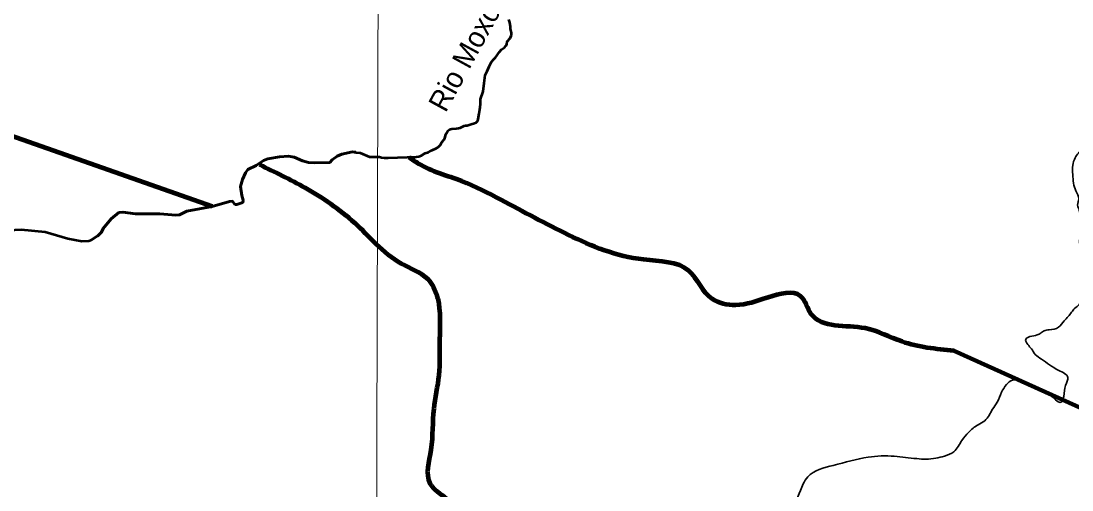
# Model space of a CAD drawing. Extents: x 553962 to 842807, y 8883888 to 9032388.
# Drawn here: x 601258 to 626649, y 8979769 to 8991098 of the extents above; entities that cross this region are included whole.
import ezdxf
from ezdxf.enums import TextEntityAlignment as Align

# ---------------------------------------------------------------- set-up
doc = ezdxf.new("R2010")
doc.units = 0
doc.header["$LTSCALE"] = 150
doc.linetypes.add('LONG_DASH_SHORT_DASH', pattern=[9.9, 6, -1.2, 1.5, -1.2])
for name, color, linetype, lineweight in [('1', 7, 'Continuous', 13), ('20', 7, 'Continuous', 35), ('24', 7, 'Continuous', 25), ('7', 7, 'LONG_DASH_SHORT_DASH', 60), ('9', 7, 'Continuous', 90)]:
    doc.layers.add(name, color=color, linetype=linetype, lineweight=lineweight)
doc.layers.add('49', color=7, linetype='Continuous')

msp = doc.modelspace()

# ---------------------------------------------------------------- linework, layer by layer
at = {"layer": '1'}
msp.add_lwpolyline([(609971.9, 9023551.8), (609764.7, 8949706.7), (609734.2, 8939404.4)], dxfattribs=at)
at = {"layer": '20'}
for points in [[(629440.7, 8990481.7), (629370.8, 8990367.6), (629157.1, 8990237.3), (629038.6, 8990213.7), (628766.6, 8990128.3), (628527.1, 8990078.5), (628266.9, 8990114.4), (627868.3, 8990076), (627513, 8989997.6), (627211.3, 8989811.1), (627131.4, 8989676.8), (627004.5, 8989388.2), (626896.7, 8988882.7), (626926.1, 8988633.1), (627053.8, 8988394.4), (627065.2, 8988197.6), (626899.8, 8988002.1), (626727, 8987796.4), (626667.6, 8987611.7), (626669.1, 8987389.7), (626688.1, 8987182.9), (626744.8, 8986994.1), (626811.6, 8986805.4), (626784.8, 8986651.2), (626823.5, 8986530.4), (626873, 8986288.6), (626889.5, 8986071.7), (626831, 8985753.3), (626882.8, 8985544.3), (626929.8, 8985304.9), (626885.6, 8984716.7), (626851.4, 8984542.3), (626820.5, 8984249.4), (626720.1, 8984162.8), (626639.9, 8984066.3), (626554.8, 8983957.2), (626457, 8983855.5), (626326.8, 8983700.6), (626095, 8983638.2), (625976.5, 8983614.6), (625901.1, 8983563.6), (625810.6, 8983515), (625631.6, 8983473.2), (625531.1, 8983404.3), (625579.8, 8983283.6), (625668.8, 8983178.3), (625763.1, 8983045.3), (625910.2, 8982930.3), (626328.4, 8982658.5), (626549.1, 8982486), (626494.8, 8982296.4), (626451.1, 8982031.1), (626383.9, 8981889.3), (626165.9, 8982026.4), (625922.7, 8982170.9), (625386.1, 8982398.9), (625214.3, 8982422.9), (625066.1, 8982313.2), (624946.2, 8982128.1), (624841.7, 8981890.1), (624729.2, 8981717.7), (624541.7, 8981441.2), (624380.8, 8981344.1), (624152.3, 8981160.7), (623989.5, 8980967.7), (623796.9, 8980693.7), (623570.4, 8980588.5), (623356.2, 8980533.9), (622896.9, 8980525.3), (622356.3, 8980584.3), (621725.5, 8980561.8), (620881.2, 8980363.6), (620267.1, 8980088.9), (620154.7, 8979914), (619893.6, 8979296.3), (619818.7, 8979169.5), (619728.9, 8978997.3), (619561.3, 8978766.4), (619441.4, 8978568.6), (619379.5, 8978391.5), (619392.8, 8978285.7), (619437, 8978086.7), (619556.3, 8977976.6), (619791.4, 8977917.8), (620167.8, 8977875.2), (620455.5, 8977869.9), (620720.6, 8977864.3), (621089.4, 8977816.7), (621432.7, 8977821.8), (621673.8, 8977601.6), (622032.5, 8977315.6)], [(622032.5, 8977315.6), (621673.8, 8977601.6), (621432.7, 8977821.8), (621089.4, 8977816.7), (620720.6, 8977864.3), (620455.5, 8977869.9), (620167.8, 8977875.2), (619791.4, 8977917.8), (619556.3, 8977976.6), (619437, 8978086.7), (619392.8, 8978285.7), (619379.5, 8978391.5), (619441.4, 8978568.6), (619561.3, 8978766.4), (619728.9, 8978997.3), (619818.7, 8979169.5), (619893.6, 8979296.3), (620154.7, 8979914), (620267.1, 8980088.9), (620881.2, 8980363.6), (621725.5, 8980561.8), (622356.3, 8980584.3), (622896.9, 8980525.3), (623356.2, 8980533.9), (623570.4, 8980588.5), (623796.9, 8980693.7), (623989.5, 8980967.7), (624152.3, 8981160.7), (624380.8, 8981344.1), (624541.7, 8981441.2), (624729.2, 8981717.7), (624841.7, 8981890.1), (624946.2, 8982128.1), (625066.1, 8982313.2), (625214.3, 8982422.9), (625386.1, 8982398.9), (625922.7, 8982170.9), (626165.9, 8982026.4), (626383.9, 8981889.3), (626451.1, 8982031.1), (626494.8, 8982296.4), (626549.1, 8982486), (626328.4, 8982658.5), (625910.2, 8982930.3), (625763.1, 8983045.3), (625668.8, 8983178.3), (625579.8, 8983283.6), (625531.1, 8983404.3), (625631.6, 8983473.2), (625810.6, 8983515), (625901.1, 8983563.6), (625976.5, 8983614.6), (626095, 8983638.2), (626326.8, 8983700.6), (626457, 8983855.5), (626554.8, 8983957.2), (626639.9, 8984066.3), (626720.1, 8984162.8), (626820.5, 8984249.4), (626851.4, 8984542.3), (626885.6, 8984716.7), (626929.8, 8985304.9), (626882.8, 8985544.3), (626831, 8985753.3), (626889.5, 8986071.7), (626873, 8986288.6), (626823.5, 8986530.4), (626784.8, 8986651.2), (626811.6, 8986805.4), (626744.8, 8986994.1), (626688.1, 8987182.9), (626669.1, 8987389.7), (626667.6, 8987611.7), (626727, 8987796.4), (626899.8, 8988002.1), (627065.2, 8988197.6), (627053.8, 8988394.4), (626926.1, 8988633.1), (626896.7, 8988882.7), (627004.5, 8989388.2), (627131.4, 8989676.8), (627211.3, 8989811.1), (627513, 8989997.6), (627868.3, 8990076), (628266.9, 8990114.4), (628527.1, 8990078.5), (628766.6, 8990128.3), (629038.6, 8990213.7), (629157.1, 8990237.3), (629370.8, 8990367.6), (629440.7, 8990481.7)]]:
    msp.add_spline(points, degree=3, dxfattribs=at)
at = {"layer": '24', "lineweight": 53}
for points in [[(612374.7, 8989257.2), (612410.1, 8989349.2), (612422.8, 8989393.2), (612443.9, 8989595.2), (612472.1, 8989790.2), (612521.4, 8989889.2), (612567.7, 8990001.2), (612623.5, 8990108.2), (612679.4, 8990175.2), (612720.8, 8990217.2), (612815.3, 8990351.2), (612864.4, 8990407.2), (612937.9, 8990460.2), (612974.6, 8990496.2), (612997.1, 8990536.2), (613004.6, 8990605.2), (613071.9, 8990685.2), (613099.4, 8990741.2), (613104.8, 8990769.2), (613104.8, 8990813.2), (613086.3, 8990905.2), (613085.9, 8990954.2), (613066.1, 8991064.2), (613044.7, 8991133.2)], [(610812.6, 8987820.3), (610868.6, 8987825.3), (610933, 8987849.3), (611023.7, 8987905.3), (611105.7, 8987931.3), (611174.3, 8987972.3), (611295.8, 8988024.3), (611334, 8988050.3), (611392.2, 8988106.3), (611428.2, 8988171.3), (611476.2, 8988225.3), (611496.6, 8988270.3), (611519.8, 8988356.3), (611535.1, 8988392.3), (611570.6, 8988443.3), (611611.3, 8988477.3), (611633.5, 8988486.3), (611663.2, 8988493.3), (611778.5, 8988500.3), (611831.3, 8988507.2), (611867.2, 8988517.2), (611960.5, 8988564.2), (611993.5, 8988570.2), (612040.4, 8988571.2), (612135.1, 8988609.2), (612211, 8988629.2), (612253, 8988646.2), (612280.4, 8988668.2), (612294.2, 8988690.2), (612304.8, 8988723.2), (612325, 8988861.2), (612344.1, 8988963.2), (612347.8, 8989019.2), (612358.9, 8989089.2), (612362.3, 8989210.2), (612374.7, 8989257.2)], [(608722.9, 8987680.8), (608777.9, 8987747.6), (608897.1, 8987833.6), (609009.5, 8987880.2), (609264.4, 8987935.4), (609356.3, 8987924.6)], [(609356.3, 8987924.6), (609448.1, 8987913.7), (609678.6, 8987816.5)], [(606420.8, 8986668), (606473.8, 8986668.1), (606613.3, 8986714.2), (606626.1, 8986769), (606594.2, 8986880), (606564.5, 8987100.6), (606609.1, 8987266.3), (606681.2, 8987431.8), (606741, 8987512.8), (606939.6, 8987610), (607118.9, 8987727.3), (607224.8, 8987767.6), (607501, 8987816.5), (607722.2, 8987831.4), (607811.1, 8987818.7)], [(607811.1, 8987818.7), (607857.5, 8987812), (608058.1, 8987723), (608202.2, 8987682.7), (608346.4, 8987672.1), (608722.9, 8987680.8)], [(609678.6, 8987816.5), (609919.3, 8987814.4), (609966, 8987801.4), (610032.6, 8987795.3), (610127.9, 8987794.3), (610812.6, 8987820.3)], [(604502.8, 8986438.7), (604614.5, 8986437.8), (604995.5, 8986406.1), (605088.3, 8986418.9), (605266.8, 8986501.7), (605873.8, 8986618.4), (606294.7, 8986737.4), (606369.1, 8986745.7), (606420.8, 8986668)], [(603138.8, 8985934.3), (603201.3, 8985995.2), (603246.4, 8986085.3), (603439.7, 8986316.8), (603622.3, 8986468.1), (603715.8, 8986478.2), (604022, 8986442.1), (604249.4, 8986440.5), (604502.8, 8986438.7)], [(600614.3, 8986048.6), (600805.6, 8986038.6), (601260, 8986057.6), (601842, 8986004.5), (602386.1, 8985845.2), (602725.9, 8985781.5), (602895.9, 8985787.9), (602963.8, 8985811.2), (603100.1, 8985896.5), (603138.8, 8985934.3)]]:
    msp.add_lwpolyline(points, dxfattribs=at)
at = {"layer": '7', "lineweight": 35}
msp.add_line((610685.7, 8987847), (610687.2, 8987846.5), dxfattribs=at)
at = {"layer": '7'}
msp.add_line((603104.5, 8985900.8), (603138.8, 8985934.3), dxfattribs=at)
for points in [[(608722.9, 8987680.8), (608777.9, 8987747.6), (608897.1, 8987833.6), (609009.5, 8987880.2), (609264.4, 8987935.4), (609347, 8987925.7)], [(606420.8, 8986668), (606473.8, 8986668.1), (606613.3, 8986714.2), (606626.1, 8986769), (606594.2, 8986880), (606564.5, 8987100.6), (606609.1, 8987266.3), (606681.2, 8987431.8), (606741, 8987512.8), (606939.6, 8987610), (607118.9, 8987727.3), (607224.8, 8987767.6), (607501, 8987816.5), (607722.2, 8987831.4), (607811.1, 8987818.7)], [(607811.1, 8987818.7), (607857.5, 8987812), (608058.1, 8987723), (608202.2, 8987682.7), (608346.4, 8987672.1), (608722.9, 8987680.8)], [(604502.8, 8986438.7), (604614.5, 8986437.8), (604995.5, 8986406.1), (605088.3, 8986418.9), (605266.8, 8986501.7), (605873.8, 8986618.4), (606294.7, 8986737.4), (606369.1, 8986745.7), (606420.8, 8986668)], [(603138.8, 8985934.3), (603201.3, 8985995.2), (603246.4, 8986085.3), (603439.7, 8986316.8), (603622.3, 8986468.1), (603715.8, 8986478.2), (604022, 8986442.1), (604249.4, 8986440.5), (604502.8, 8986438.7)]]:
    msp.add_lwpolyline(points, dxfattribs=at)
at = {"layer": '9'}
for points in [[(605873.8, 8986618.4), (590956.6, 8991866.7), (589163, 9005713.7)], [(637260.6, 8972975.8), (637390.8, 8977204.2), (635350.7, 8977923.9), (623791.9, 8983133)]]:
    msp.add_lwpolyline(points, dxfattribs=at)
for points in [[(623791.9, 8983133), (622543.6, 8983352), (621651, 8983674.8), (620351.1, 8984020), (620094.1, 8984448.6), (619305.4, 8984417.7), (618517.6, 8984234.9), (617956.8, 8984382.8), (617392.9, 8985062.3), (616297.1, 8985333.1), (614486.7, 8985927.8), (612853, 8986777), (611908.8, 8987226), (610862.9, 8987648.9), (610631.7, 8987802.8)], [(607019.9, 8987628.8), (608117.9, 8987072.5), (609319, 8986220.3), (609831, 8985717.6), (610444.6, 8985240.9), (611083, 8984865.7), (611314.6, 8984437), (611367.4, 8984108.2), (611371.5, 8983424.7), (611351.3, 8982538.5), (611228.8, 8981727.5), (611158.3, 8980739.6), (611137.7, 8979929.4), (611547.1, 8979552.5), (611828.5, 8979301.3), (612340.6, 8978773.3), (612648.8, 8978294.5), (612832.8, 8977308.5), (612940.5, 8976321.9), (612949.5, 8974803), (612829.3, 8973612.2), (613105.4, 8971372.7), (613572.8, 8968712.3), (614200.8, 8967292.3), (614110, 8965907), (613645.9, 8964639.4)]]:
    msp.add_spline(points, degree=3, dxfattribs=at)

# ---------------------------------------------------------------- texts
at = {"layer": '49'}
msp.add_text('Rio Moxotó', height=500, rotation=61.364, dxfattribs=at).set_placement((612325.1, 8990347.9), align=Align.CENTER)

doc.saveas('drawing.dxf')
